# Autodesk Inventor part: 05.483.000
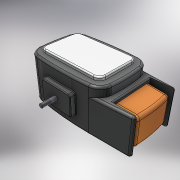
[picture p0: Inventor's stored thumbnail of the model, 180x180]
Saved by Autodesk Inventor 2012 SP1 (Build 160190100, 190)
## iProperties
Created: 2005-07
Part Number: 05.483.000
Material: Steel, Mild
Document SubType Name: Modeling
Designer: PVitaliy
Manufacturer: Standard
Standards Organization: Custom
Density: 7.86 g/cm^3
Author: PVitaliy
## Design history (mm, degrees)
derived "05.479.000.ipt"
body "Solid1"
tag "TaggingFeature2"
feature "Solid1::05.479.000.ipt" dims "d3" = 10
